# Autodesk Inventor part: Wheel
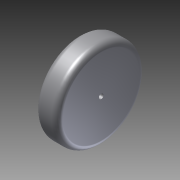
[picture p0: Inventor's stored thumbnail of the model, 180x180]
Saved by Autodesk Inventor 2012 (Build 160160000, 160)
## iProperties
Created: 2014-02
Part Number: Wheel
Material: Default
Document SubType Name: Modeling
Designer: Aser
Density: 1 g/cm^3
Author: Aser
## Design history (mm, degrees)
sketch "Sketch1"
  geometry: C1 r 75 at (0, 0); 1 further point
  constraints: 1 centre point, 1 coincident
  dimensions: "d0" = 150 diameter of C1
extrude "Extrusion1" new body sketch "Sketch1" distance "d1" = 38.1; taper "d2" = 0 deg
fillet "Fillet1" dims "d3" = 10
sketch "Sketch2"
  geometry: C1 r 65 at (0, 0) reference; C2 r 4 at (0, 0)
  constraints: 1 centre point, 1 coincident
  dimensions: "d4" = 8 diameter of C2
extrude "Extrusion2" cut sketch "Sketch2" distance "d5" = 38.1; taper "d6" = 0 deg
body "Solid1"
